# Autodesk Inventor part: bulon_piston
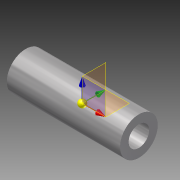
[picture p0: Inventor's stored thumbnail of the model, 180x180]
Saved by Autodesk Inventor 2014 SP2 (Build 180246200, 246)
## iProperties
Created: 2015-07
Part Number: bulon_piston
Material: Acero, aleación
Document SubType Name: Modeling
Designer: Jaime
Mass: 141.8 g
Surface Area: 75.838 cm^2
Volume: 17.6243 cm^3
Density: 8.04569 g/cm^3
Appearance: Semipulido
Author: Jaime
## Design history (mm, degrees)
sketch "Boceto1"
  geometry: C1 r 11 at (0, 0); C2 r 6 at (0, 0); 1 further point
  constraints: 2 centre point, 2 coincident
  dimensions: "d0" = 22 diameter of C1; "d3" = 12 diameter of C2
extrude "Extrusión2" new body sketch "Boceto1" stored distance "d4" = 66; taper "d5" = 0 deg
node "Sólido2"
